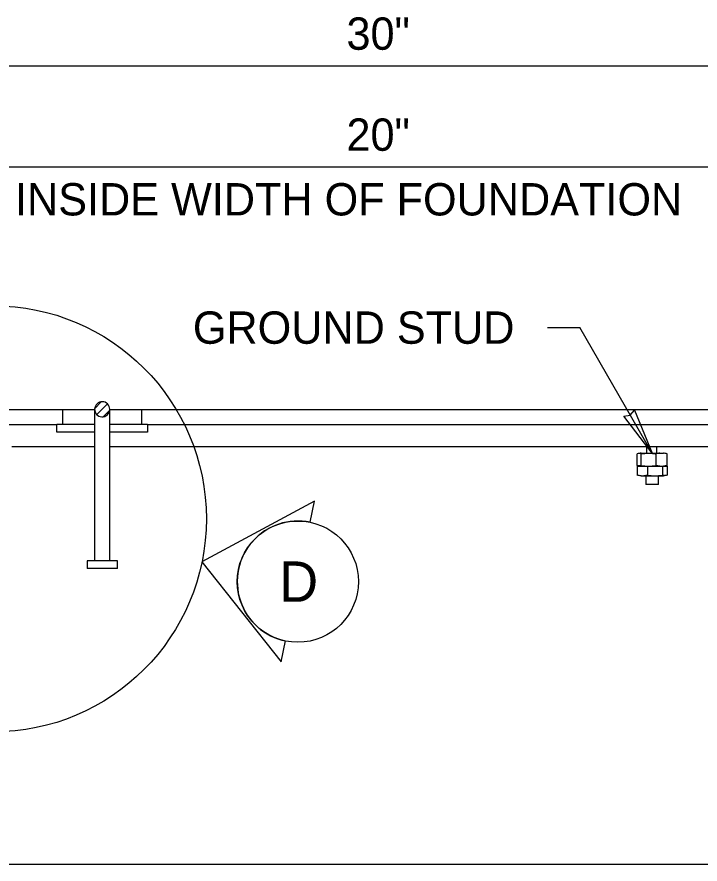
# Model space of a CAD drawing. Extents: x 99862 to 112891, y 95370 to 105076.
# Drawn here: x 101750.4 to 102088.7, y 100273.8 to 100693.1 of the extents above; entities that cross this region are included whole.
import ezdxf

# ---------------------------------------------------------------- set-up
doc = ezdxf.new("R2010")
doc.units = 0
for name, color, linetype in [('Level 15', 7, 'Continuous'), ('Level 2', 7, 'Continuous'), ('Level 20', 7, 'Continuous'), ('Level 22', 7, 'Continuous'), ('Level 3', 7, 'Continuous'), ('Level 4', 7, 'Continuous'), ('Level 5', 7, 'Continuous')]:
    doc.layers.add(name, color=color, linetype=linetype)

msp = doc.modelspace()

# ---------------------------------------------------------------- linework, layer by layer
at = {"layer": 'Level 15'}
for p, q in [((101659.02, 100668.81), (102199.02, 100668.81)), ((101704.02, 100618.81), (102154.03, 100618.81)), ((102013.11, 100539.31), (102029.11, 100539.31)), ((102065.02, 100477.13), (102029.11, 100539.31))]:
    msp.add_line(p, q, dxfattribs=at)
msp.add_lwpolyline([(102065.02, 100477.13), (102051.02, 100495.41), (102054.13, 100495.99), (102056.19, 100498.39)], close=True, dxfattribs=at)
msp.add_circle((101738.77, 100444.66), 105.46, dxfattribs=at)
at = {"layer": 'Level 2'}
for p, q in [((101788.9, 100480.28), (101747.95, 100480.28)), ((102154.03, 100480.28), (101796.4, 100480.28))]:
    msp.add_line(p, q, dxfattribs=at)
at = {"layer": 'Level 20'}
for p, q in [((101897.72, 100453.36), (101842.06, 100423.37)), ((101895.58, 100442.98), (101897.72, 100453.36)), ((101842.06, 100423.37), (101881.33, 100373.83)), ((101881.33, 100373.83), (101883.47, 100384.21))]:
    msp.add_line(p, q, dxfattribs=at)
msp.add_circle((101889.53, 100413.59), 30, dxfattribs=at)
msp.add_arc((101889.53, 100413.59), 30, 78.3549, 258.3593, dxfattribs=at)
at = {"layer": 'Level 22'}
for points in [[(102057.65, 100471.04), (102057.65, 100471.03), (102057.65, 100471.03), (102057.65, 100471.03)], [(102057.65, 100466.25), (102057.65, 100466.25), (102057.65, 100466.25), (102057.65, 100466.25)]]:
    msp.add_open_spline(points, degree=2, dxfattribs=at)
at = {"layer": 'Level 3'}
for p, q in [((101744.26, 100498.81), (101772.96, 100498.81)), ((101772.96, 100498.81), (101772.96, 100491.31)), ((101772.96, 100498.81), (101788.9, 100498.81)), ((101796.4, 100498.81), (101812.33, 100498.81)), ((101812.33, 100498.81), (102169.95, 100498.81)), ((101812.33, 100491.31), (101812.33, 100498.81)), ((101744.26, 100491.31), (101770.15, 100491.31)), ((101815.15, 100491.31), (102154.03, 100491.31))]:
    msp.add_line(p, q, dxfattribs=at)
at = {"layer": 'Level 4'}
for p, q in [((101788.92, 100499.35), (101792.18, 100502.61)), ((101795.26, 100501.58), (101789.95, 100496.28)), ((101788.9, 100499.04), (101788.9, 100423.89)), ((101796.37, 100498.45), (101793.08, 100495.16)), ((101796.4, 100423.89), (101796.4, 100498.89)), ((101770.15, 100487.56), (101770.15, 100491.31)), ((101788.9, 100491.31), (101770.15, 100491.31)), ((101788.9, 100487.56), (101770.15, 100487.56)), ((101788.9, 100491.39), (101788.9, 100491.31)), ((101796.4, 100491.39), (101796.4, 100491.39)), ((101796.4, 100491.31), (101796.4, 100491.39)), ((101815.15, 100491.31), (101796.4, 100491.31)), ((101815.15, 100487.56), (101796.4, 100487.56)), ((101815.15, 100491.31), (101815.15, 100487.56)), ((101800.15, 100423.89), (101785.15, 100423.89)), ((101785.15, 100423.89), (101785.15, 100420.14)), ((101800.15, 100420.14), (101800.15, 100423.89)), ((101800.15, 100420.14), (101785.15, 100420.14))]:
    msp.add_line(p, q, dxfattribs=at)
msp.add_arc((101792.65, 100498.89), 3.75, 0, 355.2356, dxfattribs=at)
at = {"layer": 'Level 5'}
for p, q in [((102062.38, 100477.13), (102062.38, 100480.28)), ((102067.28, 100477.13), (102067.28, 100480.28)), ((102057.65, 100471.04), (102057.65, 100476.85)), ((102059.49, 100477.13), (102065.02, 100477.13)), ((102059.59, 100471.04), (102059.59, 100476.85)), ((102065.02, 100477.13), (102070.54, 100477.13)), ((102066.96, 100471.04), (102066.96, 100476.85)), ((102072.38, 100471.04), (102072.38, 100476.85)), ((102057.65, 100470.75), (102057.65, 100466.25)), ((102057.65, 100470.75), (102061.33, 100470.75)), ((102061.33, 100470.75), (102068.7, 100470.75)), ((102062.74, 100470.75), (102062.74, 100466.25)), ((102068.7, 100470.75), (102072.38, 100470.75)), ((102070.1, 100470.75), (102070.1, 100466.25)), ((102072.38, 100470.75), (102072.38, 100466.25)), ((102059.49, 100465.97), (102065.02, 100465.97)), ((102061.82, 100465.97), (102061.82, 100461.64)), ((102065.02, 100465.97), (102070.54, 100465.97)), ((102068.21, 100461.64), (102068.21, 100465.97)), ((102068.21, 100461.64), (102061.82, 100461.64)), ((101584.02, 100273.81), (102274.02, 100273.81))]:
    msp.add_line(p, q, dxfattribs=at)
for points in [[(102059.49, 100477.13), (102059.18, 100477.13), (102058.57, 100477.08), (102057.95, 100476.94), (102057.65, 100476.85)], [(102059.59, 100476.85), (102059.29, 100476.94), (102058.96, 100477.01), (102058.64, 100477.06), (102058.62, 100477.06)], [(102059.59, 100476.85), (102060.2, 100476.94), (102060.82, 100477.01), (102062.05, 100477.1), (102062.66, 100477.13), (102063.28, 100477.13)], [(102063.28, 100477.13), (102063.89, 100477.13), (102065.12, 100477.08), (102066.35, 100476.94), (102066.96, 100476.85)], [(102068.8, 100477.13), (102068.49, 100477.13), (102067.88, 100477.08), (102067.27, 100476.94), (102066.96, 100476.85)], [(102072.38, 100476.85), (102072.08, 100476.94), (102071.46, 100477.08), (102070.85, 100477.13), (102070.54, 100477.13)], [(102059.49, 100470.75), (102059.18, 100470.75), (102058.57, 100470.81), (102057.95, 100470.95), (102057.65, 100471.04)], [(102059.59, 100471.04), (102059.29, 100470.95), (102058.96, 100470.87), (102058.64, 100470.82), (102058.62, 100470.82)], [(102059.59, 100471.04), (102060.2, 100470.95), (102060.82, 100470.88), (102062.05, 100470.78), (102062.66, 100470.75), (102063.28, 100470.75)], [(102063.28, 100470.75), (102063.89, 100470.75), (102065.12, 100470.81), (102066.35, 100470.95), (102066.96, 100471.04)], [(102068.8, 100470.75), (102068.49, 100470.75), (102067.88, 100470.81), (102067.27, 100470.95), (102066.96, 100471.04)], [(102072.38, 100471.04), (102072.08, 100470.95), (102071.46, 100470.8), (102070.85, 100470.75), (102070.54, 100470.75)], [(102059.49, 100465.97), (102059.18, 100465.97), (102058.57, 100466.02), (102057.95, 100466.16), (102057.65, 100466.25)], [(102062.74, 100466.25), (102062.43, 100466.16), (102061.81, 100466.02), (102061.2, 100465.97), (102060.89, 100465.97)], [(102062.74, 100466.25), (102063.35, 100466.16), (102063.96, 100466.09), (102065.19, 100465.99), (102065.81, 100465.97), (102066.42, 100465.97)], [(102066.42, 100465.97), (102067.03, 100465.97), (102068.26, 100466.02), (102069.49, 100466.16), (102070.1, 100466.25)], [(102071.24, 100466.01), (102071.17, 100466.02), (102070.79, 100466.07), (102070.41, 100466.16), (102070.1, 100466.25)], [(102072.38, 100466.25), (102072.08, 100466.16), (102071.46, 100466.02), (102070.85, 100465.97), (102070.54, 100465.97)]]:
    msp.add_open_spline(points, degree=3, dxfattribs=at)

# ---------------------------------------------------------------- texts
at = {"layer": 'Level 20'}
for s, height, p in [('30"', 16, (101913.62, 100676.81)), ('20"', 16, (101913.62, 100626.81)), ('INSIDE WIDTH OF FOUNDATION', 16, (101749.46, 100594.81)), ('GROUND STUD', 16, (101837.53, 100531.31)), ('D', 20, (101880.28, 100403.59))]:
    msp.add_text(s, height=height, dxfattribs=at).set_placement(p)

doc.saveas('drawing.dxf')
